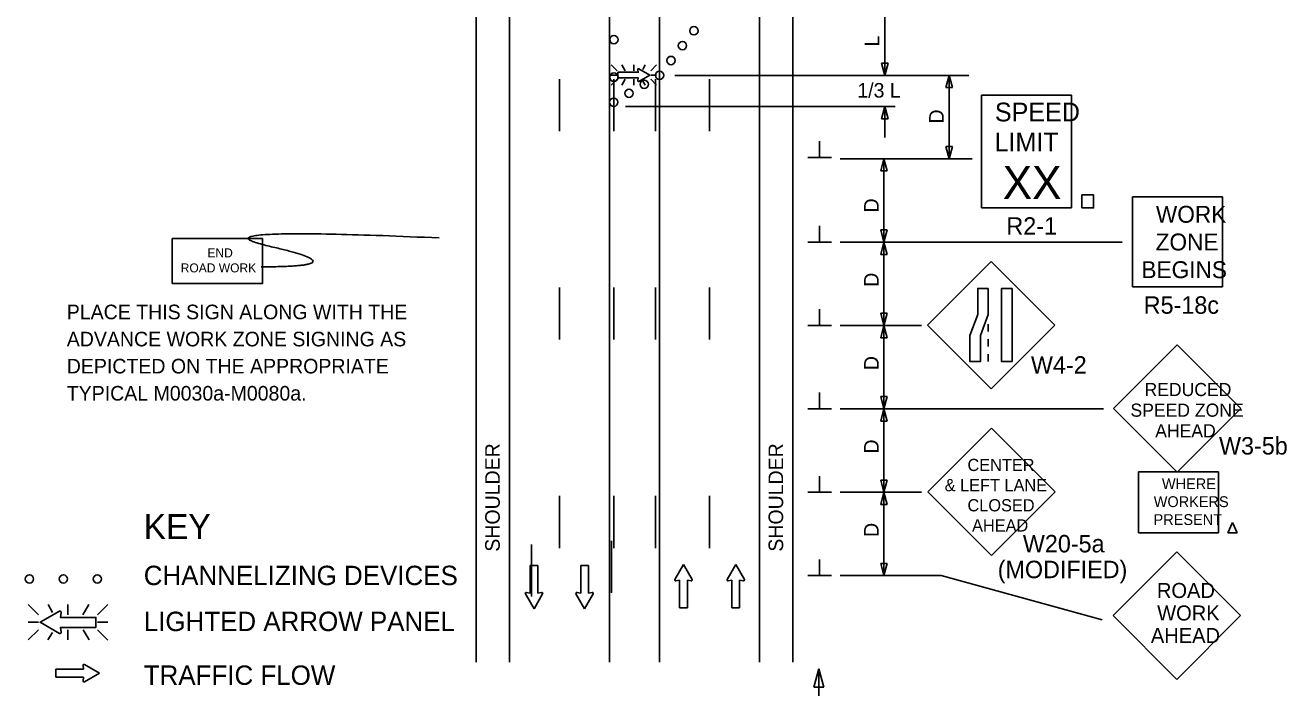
# Model space of a CAD drawing. Extents: x 16730 to 18475, y 5651 to 6927.
# Drawn here: x 16731 to 17336, y 6084 to 6401 of the extents above; entities that cross this region are included whole.
import ezdxf

# ---------------------------------------------------------------- set-up
doc = ezdxf.new("R2010")
doc.units = 0
for name, color, linetype in [('ALI_LEGAL_EX', 7, 'Continuous'), ('MT_SCRATCH_LEVEL_E', 7, 'Continuous'), ('PAVT_EDGE_EX', 7, 'Continuous'), ('TRAFFIC_SIGNS_PR', 7, 'Continuous'), ('TYPICAL_TEXT_DIMEN_EX', 7, 'Continuous'), ('TYPICAL_TEXT_DIMEN_PR', 7, 'Continuous')]:
    doc.layers.add(name, color=color, linetype=linetype)

msp = doc.modelspace()

# ---------------------------------------------------------------- linework, layer by layer
at = {"layer": 'ALI_LEGAL_EX'}
for points in [[(16987.43, 6375.6), (16987.43, 6350.6)], [(17013.43, 6375.6), (17013.43, 6350.6)], [(17033.43, 6375.6), (17033.43, 6350.6)], [(17059.43, 6375.6), (17059.43, 6350.6)], [(16987.43, 6275.6), (16987.43, 6250.6)], [(17013.43, 6275.6), (17013.43, 6250.6)], [(17033.43, 6275.6), (17033.43, 6250.6)], [(17059.43, 6275.6), (17059.43, 6250.6)], [(16987.43, 6175.6), (16987.43, 6150.6)], [(17013.43, 6175.6), (17013.43, 6150.6)], [(17033.43, 6175.6), (17033.43, 6150.6)], [(17059.43, 6175.6), (17059.43, 6150.6)]]:
    msp.add_lwpolyline(points, dxfattribs=at)
at = {"layer": 'MT_SCRATCH_LEVEL_E'}
for p, q in [((16977.1, 6142.27), (16973.36, 6142.27)), ((16973.36, 6142.27), (16973.36, 6129.01)), ((16977.1, 6142.27), (16973.36, 6142.27)), ((16973.36, 6142.27), (16973.36, 6129.01)), ((16977.1, 6129.01), (16977.1, 6142.27)), ((16977.1, 6129.01), (16977.1, 6142.27)), ((17001.36, 6142.27), (16997.62, 6142.27)), ((16997.62, 6142.27), (16997.62, 6129.01)), ((17001.36, 6142.27), (16997.62, 6142.27)), ((16997.62, 6142.27), (16997.62, 6129.01)), ((17001.36, 6129.01), (17001.36, 6142.27)), ((17001.36, 6129.01), (17001.36, 6142.27)), ((17046.87, 6142.73), (17042.76, 6135.49)), ((17046.87, 6142.73), (17042.76, 6135.49)), ((17051.02, 6135.49), (17046.87, 6142.73)), ((17051.02, 6135.49), (17046.87, 6142.73)), ((17071.96, 6142.73), (17067.85, 6135.49)), ((17071.96, 6142.73), (17067.85, 6135.49)), ((17076.11, 6135.49), (17071.96, 6142.73)), ((17076.11, 6135.49), (17071.96, 6142.73)), ((17043.24, 6134.81), (17045.02, 6135.12)), ((17043.24, 6134.81), (17045.02, 6135.12)), ((17045.02, 6135.12), (17045.02, 6121.86)), ((17045.02, 6135.12), (17045.02, 6121.86)), ((17048.76, 6121.86), (17048.76, 6135.12)), ((17048.76, 6135.12), (17050.54, 6134.81)), ((17048.76, 6121.86), (17048.76, 6135.12)), ((17048.76, 6135.12), (17050.54, 6134.81)), ((17068.33, 6134.81), (17070.11, 6135.12)), ((17068.33, 6134.81), (17070.11, 6135.12)), ((17070.11, 6135.12), (17070.11, 6121.86)), ((17070.11, 6135.12), (17070.11, 6121.86)), ((17073.85, 6121.86), (17073.85, 6135.12)), ((17073.85, 6135.12), (17075.63, 6134.81)), ((17073.85, 6121.86), (17073.85, 6135.12)), ((17073.85, 6135.12), (17075.63, 6134.81)), ((16973.36, 6129.01), (16971.58, 6129.33)), ((16973.36, 6129.01), (16971.58, 6129.33)), ((16978.88, 6129.33), (16977.1, 6129.01)), ((16978.88, 6129.33), (16977.1, 6129.01)), ((16997.62, 6129.01), (16995.84, 6129.33)), ((16997.62, 6129.01), (16995.84, 6129.33)), ((17003.14, 6129.33), (17001.36, 6129.01)), ((17003.14, 6129.33), (17001.36, 6129.01)), ((16971.1, 6128.64), (16975.25, 6121.4)), ((16971.1, 6128.64), (16975.25, 6121.4)), ((16975.25, 6121.4), (16979.36, 6128.64)), ((16975.25, 6121.4), (16979.36, 6128.64)), ((16995.36, 6128.64), (16999.51, 6121.4)), ((16995.36, 6128.64), (16999.51, 6121.4)), ((16999.51, 6121.4), (17003.62, 6128.64)), ((16999.51, 6121.4), (17003.62, 6128.64)), ((17045.02, 6121.86), (17048.76, 6121.86)), ((17045.02, 6121.86), (17048.76, 6121.86)), ((17070.11, 6121.86), (17073.85, 6121.86)), ((17070.11, 6121.86), (17073.85, 6121.86)), ((16758.93, 6094.23), (16759.24, 6092.45)), ((16758.93, 6094.23), (16759.24, 6092.45)), ((16766.85, 6090.6), (16759.61, 6094.71)), ((16766.85, 6090.6), (16759.61, 6094.71)), ((16759.24, 6092.45), (16745.98, 6092.45)), ((16745.98, 6092.45), (16745.98, 6088.71)), ((16759.24, 6092.45), (16745.98, 6092.45)), ((16745.98, 6092.45), (16745.98, 6088.71)), ((16745.98, 6088.71), (16759.24, 6088.71)), ((16745.98, 6088.71), (16759.24, 6088.71)), ((16759.24, 6088.71), (16758.93, 6086.93)), ((16759.24, 6088.71), (16758.93, 6086.93)), ((16759.61, 6086.45), (16766.85, 6090.6)), ((16759.61, 6086.45), (16766.85, 6090.6))]:
    msp.add_line(p, q, dxfattribs=at)
for centre, start, end in [((17043.17, 6135.26), 150.42484, 279.96381), ((17043.17, 6135.26), 150.42484, 279.96381), ((17050.61, 6135.27), 260.03619, 29.77312), ((17050.61, 6135.27), 260.03619, 29.77312), ((17068.26, 6135.26), 150.42484, 279.96381), ((17068.26, 6135.26), 150.42484, 279.96381), ((17075.7, 6135.27), 260.03619, 29.77312), ((17075.7, 6135.27), 260.03619, 29.77312), ((16971.51, 6128.87), 80.03619, 209.77312), ((16971.51, 6128.87), 80.03619, 209.77312), ((16978.96, 6128.87), 330.42484, 99.96381), ((16978.96, 6128.87), 330.42484, 99.96381), ((16995.77, 6128.87), 80.03619, 209.77312), ((16995.77, 6128.87), 80.03619, 209.77312), ((17003.21, 6128.87), 330.42484, 99.96381), ((17003.21, 6128.87), 330.42484, 99.96381), ((16759.39, 6094.3), 60.42484, 189.96381), ((16759.39, 6094.3), 60.42484, 189.96381), ((16759.39, 6086.86), 170.03619, 299.77312), ((16759.39, 6086.86), 170.03619, 299.77312)]:
    msp.add_arc(centre, 0.463, start, end, dxfattribs=at)
at = {"layer": 'PAVT_EDGE_EX'}
for p, q in [((16947.43, 6893.09), (16947.43, 6095.81)), ((16963.43, 6893.09), (16963.43, 6095.81)), ((17011.43, 6893.09), (17011.43, 6095.81)), ((17035.43, 6893.09), (17035.43, 6095.81)), ((17083.43, 6893.09), (17083.43, 6095.81)), ((17099.43, 6893.09), (17099.43, 6095.81))]:
    msp.add_line(p, q, dxfattribs=at)
for points in [[(17012.43, 6129.06), (17012.43, 6154.06)], [(16974.07, 6127.31), (16974.07, 6152.31)]]:
    msp.add_lwpolyline(points, dxfattribs=at)
at = {"layer": 'TRAFFIC_SIGNS_PR'}
for p, q in [((17015.05, 6379.51), (17012.23, 6382.33)), ((17015.05, 6377.48), (17012.23, 6377.48)), ((17017.35, 6382.33), (17018.98, 6379.51)), ((17023.14, 6379.51), (17023.14, 6382.33)), ((17028.61, 6382.33), (17027.4, 6380.24)), ((17034.04, 6382.33), (17031.22, 6379.51)), ((17031.22, 6377.48), (17034.04, 6377.48)), ((17015.05, 6375.45), (17012.23, 6372.62)), ((17019, 6375.45), (17017.38, 6372.63)), ((17023.14, 6375.45), (17023.14, 6372.63)), ((17027.32, 6374.81), (17028.58, 6372.63)), ((17034.04, 6372.63), (17031.22, 6375.45)), ((17189.76, 6367.8), (17232.96, 6367.8)), ((17189.76, 6313.8), (17189.76, 6367.8)), ((17232.96, 6313.8), (17232.96, 6367.8)), ((17262.23, 6275.85), (17262.23, 6319.05)), ((17262.23, 6319.05), (17305.43, 6319.05)), ((17305.43, 6275.85), (17305.43, 6319.05)), ((17189.76, 6313.8), (17232.96, 6313.8)), ((17194.5, 6288.03), (17163.95, 6257.48)), ((17225.04, 6257.48), (17194.5, 6288.03)), ((17262.23, 6275.85), (17305.43, 6275.85)), ((17163.95, 6257.48), (17194.5, 6226.93)), ((17193.09, 6258.03), (17193.09, 6254.43)), ((17194.5, 6226.93), (17225.04, 6257.48)), ((17193.09, 6250.83), (17193.09, 6247.23)), ((17283.71, 6248.07), (17253.16, 6217.52)), ((17314.26, 6217.52), (17283.71, 6248.07)), ((17193.09, 6243.63), (17193.09, 6240.03)), ((17253.16, 6217.52), (17283.71, 6186.97)), ((17283.71, 6186.97), (17314.26, 6217.52)), ((17194.61, 6208.13), (17164.06, 6177.59)), ((17225.16, 6177.59), (17194.61, 6208.13)), ((17265.06, 6187.16), (17303.46, 6187.16)), ((17265.06, 6157.84), (17265.06, 6187.16)), ((17303.46, 6157.84), (17303.46, 6187.16)), ((17164.06, 6177.59), (17194.61, 6147.04)), ((17194.61, 6147.04), (17225.16, 6177.59)), ((17265.06, 6157.84), (17303.46, 6157.84)), ((17283.48, 6148.71), (17252.93, 6118.16)), ((17314.03, 6118.16), (17283.48, 6148.71)), ((16732.6, 6123.46), (16737.54, 6118.53)), ((16744.37, 6119.64), (16742.16, 6123.47)), ((16751.69, 6118.53), (16751.69, 6123.47)), ((16758.92, 6118.53), (16761.77, 6123.47)), ((16765.84, 6118.53), (16770.77, 6123.47)), ((17252.93, 6118.16), (17283.48, 6087.61)), ((17283.48, 6087.61), (17314.03, 6118.16)), ((16737.54, 6114.98), (16732.6, 6114.98)), ((16732.6, 6106.49), (16737.54, 6111.42)), ((16751.69, 6111.42), (16751.69, 6106.49)), ((16761.82, 6106.49), (16758.97, 6111.42)), ((16765.84, 6114.98), (16770.77, 6114.98)), ((16765.84, 6111.42), (16770.77, 6106.48)), ((16742.12, 6106.49), (16744.23, 6110.15))]:
    msp.add_line(p, q, dxfattribs=at)
for points in [[(17024.97, 6380.16), (17025.19, 6378.86), (17015.47, 6378.86), (17015.47, 6376.12), (17025.19, 6376.12), (17024.96, 6374.82)], [(17025.47, 6374.46), (17030.77, 6377.48), (17025.46, 6380.52)], [(17310.21, 6162.78), (17307.97, 6157.84)], [(17307.97, 6157.84), (17310.21, 6162.78)], [(17312.44, 6157.84), (17310.21, 6162.78)], [(17310.21, 6162.78), (17312.44, 6157.84)], [(17307.97, 6157.84), (17312.44, 6157.84)], [(17312.44, 6157.84), (17307.97, 6157.84)], [(16747.61, 6120.25), (16738.32, 6114.98), (16747.62, 6109.65)], [(16748.49, 6110.28), (16748.09, 6112.55), (16765.1, 6112.55), (16765.1, 6117.35), (16748.09, 6117.35), (16748.49, 6119.63)]]:
    msp.add_lwpolyline(points, dxfattribs=at)
for points in [[(17237.98, 6313.8), (17243.57, 6313.8), (17243.57, 6319.98), (17237.98, 6319.98)], [(16801.74, 6277.49), (16844.94, 6277.49), (16844.94, 6299.09), (16801.74, 6299.09)], [(17193.09, 6275.18), (17193.09, 6262.6), (17189.33, 6252.61), (17189.33, 6240.03), (17184.28, 6240.03), (17184.28, 6252.61), (17188.04, 6262.6), (17188.04, 6275.18)], [(17204.5, 6275.18), (17204.5, 6240.03), (17199.44, 6240.03), (17199.44, 6275.18)]]:
    msp.add_lwpolyline(points, close=True, dxfattribs=at)
for centre in [(17013.53, 6394.49), (17051.92, 6398.74), (17046.42, 6391.61), (17040.93, 6384.48), (17013.53, 6376.49), (17035.43, 6377.36), (17028.11, 6373.05), (17013.45, 6364.44), (17020.78, 6368.74), (16733.22, 6135.75), (16749.52, 6135.75), (16765.82, 6135.75)]:
    msp.add_circle(centre, 2, dxfattribs=at)
for centre, radius, start, end in [((17025.3, 6380.22), 0.341, 61.48329, 189.95933), ((17025.3, 6374.76), 0.341, 170.73078, 298.89165), ((16747.9, 6119.73), 0.598, 350.73078, 118.89165), ((16747.9, 6110.18), 0.597, 241.48329, 9.95933)]:
    msp.add_arc(centre, radius, start, end, dxfattribs=at)
msp.add_open_spline([(16844.42, 6285.5), (16891.66, 6285.5), (16806.64, 6304.85), (16929.73, 6299.36)], degree=2, dxfattribs=at)
at = {"layer": 'TYPICAL_TEXT_DIMEN_PR'}
for p, q in [((17143.43, 6377.36), (17143.43, 6407.93)), ((17143.43, 6377.36), (17141.86, 6383.22)), ((17141.86, 6383.22), (17143.43, 6383.22)), ((17143.43, 6383.22), (17145, 6383.22)), ((17145, 6383.22), (17143.43, 6377.36)), ((17183.8, 6377.36), (17042.79, 6377.36)), ((17172.71, 6371.49), (17174.28, 6377.36)), ((17174.28, 6377.36), (17175.85, 6371.49)), ((17174.28, 6377.36), (17174.28, 6337.36)), ((17174.28, 6371.49), (17172.71, 6371.49)), ((17175.85, 6371.49), (17174.28, 6371.49)), ((17148.43, 6362.43), (17019.11, 6362.43)), ((17143.43, 6362.43), (17141.86, 6356.57)), ((17143.43, 6362.43), (17143.43, 6347.51)), ((17145, 6356.57), (17143.43, 6362.43)), ((17141.86, 6356.57), (17143.43, 6356.57)), ((17143.43, 6356.57), (17145, 6356.57)), ((17112.19, 6338.01), (17112.19, 6345.79)), ((17174.28, 6337.36), (17172.71, 6343.22)), ((17172.71, 6343.22), (17174.28, 6343.22)), ((17174.28, 6343.22), (17175.85, 6343.22)), ((17175.85, 6343.22), (17174.28, 6337.36)), ((17117.82, 6338.01), (17106.57, 6338.01)), ((17122.07, 6337.36), (17185.32, 6337.36)), ((17141.5, 6331.49), (17143.07, 6337.36)), ((17143.07, 6337.36), (17143.07, 6297.36)), ((17143.07, 6337.36), (17144.64, 6331.49)), ((17143.07, 6331.49), (17141.5, 6331.49)), ((17144.64, 6331.49), (17143.07, 6331.49)), ((17112.19, 6297.36), (17112.19, 6305.14)), ((17143.07, 6297.36), (17141.5, 6303.22)), ((17141.5, 6303.22), (17143.07, 6303.22)), ((17143.07, 6303.22), (17144.64, 6303.22)), ((17144.64, 6303.22), (17143.07, 6297.36)), ((17117.82, 6297.36), (17106.57, 6297.36)), ((17122.07, 6297.36), (17257.25, 6297.36)), ((17141.5, 6291.49), (17143.07, 6297.36)), ((17143.07, 6297.36), (17143.07, 6257.36)), ((17143.07, 6297.36), (17144.64, 6291.49)), ((17143.07, 6291.49), (17141.5, 6291.49)), ((17144.64, 6291.49), (17143.07, 6291.49)), ((17112.19, 6257.36), (17112.19, 6265.14)), ((17143.07, 6257.36), (17141.5, 6263.22)), ((17141.5, 6263.22), (17143.07, 6263.22)), ((17143.07, 6263.22), (17144.64, 6263.22)), ((17144.64, 6263.22), (17143.07, 6257.36)), ((17117.82, 6257.36), (17106.57, 6257.36)), ((17122.07, 6257.36), (17161.07, 6257.36)), ((17141.5, 6251.49), (17143.07, 6257.36)), ((17143.07, 6257.36), (17143.07, 6217.36)), ((17143.07, 6257.36), (17144.64, 6251.49)), ((17143.07, 6251.49), (17141.5, 6251.49)), ((17144.64, 6251.49), (17143.07, 6251.49)), ((17112.19, 6217.36), (17112.19, 6225.14)), ((17143.07, 6217.36), (17141.5, 6223.22)), ((17141.5, 6223.22), (17143.07, 6223.22)), ((17143.07, 6223.22), (17144.64, 6223.22)), ((17144.64, 6223.22), (17143.07, 6217.36)), ((17117.82, 6217.36), (17106.57, 6217.36)), ((17122.07, 6217.36), (17248.39, 6217.36)), ((17141.5, 6211.49), (17143.07, 6217.36)), ((17143.07, 6217.36), (17143.07, 6177.36)), ((17143.07, 6217.36), (17144.64, 6211.49)), ((17143.07, 6211.49), (17141.5, 6211.49)), ((17144.64, 6211.49), (17143.07, 6211.49)), ((17112.19, 6177.36), (17112.19, 6185.14)), ((17117.82, 6177.36), (17106.57, 6177.36)), ((17122.07, 6177.36), (17161.07, 6177.36)), ((17143.07, 6177.36), (17141.5, 6183.22)), ((17141.5, 6183.22), (17143.07, 6183.22)), ((17141.5, 6171.49), (17143.07, 6177.36)), ((17143.07, 6183.22), (17144.64, 6183.22)), ((17144.64, 6183.22), (17143.07, 6177.36)), ((17143.07, 6177.36), (17143.07, 6137.36)), ((17143.07, 6177.36), (17144.64, 6171.49)), ((17143.07, 6171.49), (17141.5, 6171.49)), ((17144.64, 6171.49), (17143.07, 6171.49)), ((17112.19, 6137.36), (17112.19, 6145.14)), ((17143.07, 6137.36), (17141.5, 6143.22)), ((17141.5, 6143.22), (17143.07, 6143.22)), ((17143.07, 6143.22), (17144.64, 6143.22)), ((17144.64, 6143.22), (17143.07, 6137.36)), ((17117.82, 6137.36), (17106.57, 6137.36)), ((17122.07, 6137.36), (17170.46, 6137.36)), ((17170.46, 6137.36), (17247.64, 6116.12)), ((17109.5, 6083.88), (17111.86, 6092.68)), ((17111.86, 6075.55), (17111.86, 6092.68)), ((17111.86, 6092.68), (17114.22, 6083.88)), ((17111.86, 6083.88), (17109.5, 6083.88)), ((17114.22, 6083.88), (17111.86, 6083.88))]:
    msp.add_line(p, q, dxfattribs=at)

# ---------------------------------------------------------------- texts
at = {"layer": 'TRAFFIC_SIGNS_PR'}
for s, height, p in [('SPEED', 9, (17196.25, 6355.27)), ('LIMIT', 9, (17196.07, 6340.87)), ('XX', 15.785, (17200.02, 6318.03)), ('WORK', 8.119, (17273.48, 6306.64)), ('R2-1', 8.37, (17201.78, 6300.93)), ('ZONE', 8.119, (17273.35, 6293.35)), ('END', 4.31, (16818.61, 6290.02)), ('ROAD WORK', 4.31, (16805.8, 6282.83)), ('BEGINS', 8.119, (17266.52, 6280.07)), ('R5-18c', 8.37, (17267.64, 6262.98)), ('PLACE THIS SIGN ALONG WITH THE', 7, (16751.15, 6260.35)), ('ADVANCE WORK ZONE SIGNING AS', 7, (16751.15, 6247.35)), ('DEPICTED ON THE APPROPRIATE', 7, (16751.15, 6234.35)), ('W4-2', 8.37, (17213.54, 6234.25)), ('TYPICAL M0030a-M0080a.', 7, (16751.15, 6221.35)), ('REDUCED', 6.3, (17268.02, 6223.49)), ('SPEED ZONE', 6.3, (17261.27, 6213.59)), ('AHEAD', 6.3, (17273.15, 6203.69)), ('W3-5b', 8.37, (17303.74, 6195.45)), ('CENTER', 5.85, (17183.11, 6187.54)), ('& LEFT LANE', 5.85, (17172.16, 6177.86)), ('WHERE', 5.2, (17276.37, 6178.84)), ('CLOSED', 5.85, (17183.12, 6168.19)), ('WORKERS', 5.2, (17272.44, 6170.24)), ('PRESENT', 5.2, (17272.37, 6161.64)), ('AHEAD', 5.85, (17185.3, 6158.51)), ('W20-5a', 8.37, (17209.66, 6148.51)), ('(MODIFIED)', 8.37, (17197.61, 6136.14)), ('ROAD', 7.2, (17273.96, 6126.64)), ('WORK', 7.2, (17274.09, 6115.84)), ('AHEAD', 7.2, (17271.06, 6105.04))]:
    msp.add_text(s, height=height, dxfattribs=at).set_placement(p)
at = {"layer": 'TYPICAL_TEXT_DIMEN_EX'}
for s, height, p in [('KEY', 12, (16788.06, 6154.86)), ('CHANNELIZING DEVICES', 9.3, (16788.06, 6132.81)), ('LIGHTED ARROW PANEL', 9.3, (16788.06, 6110.76)), ('TRAFFIC FLOW', 9.3, (16788.06, 6084.96))]:
    msp.add_text(s, height=height, dxfattribs=at).set_placement(p)
at = {"layer": 'TYPICAL_TEXT_DIMEN_PR'}
for s, p in [('L', (17140.88, 6391.22)), ('D', (17171.72, 6354.24)), ('D', (17140.51, 6311.57)), ('D', (17140.51, 6275.92)), ('D', (17140.51, 6235.92)), ('D', (17140.51, 6195.92)), ('SHOULDER', (16958.81, 6148.84)), ('SHOULDER', (17094.71, 6148.84)), ('D', (17140.51, 6155.92))]:
    msp.add_text(s, height=7, rotation=90, dxfattribs=at).set_placement(p)
msp.add_text('1/3 L', height=7, dxfattribs=at).set_placement((17130.28, 6366.67))

doc.saveas('drawing.dxf')
